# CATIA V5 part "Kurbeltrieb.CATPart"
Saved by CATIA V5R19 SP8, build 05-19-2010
Part number: Kurbeltrieb
Bounding box of the stored display mesh (mm): x -155 to 155, y -203.9 to 203.9, z -24.965 to 24.965
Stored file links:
  C:\Users\schneidp\Desktop\Manikan\V5R19\Kurbeltrieb.CATPart
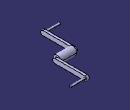
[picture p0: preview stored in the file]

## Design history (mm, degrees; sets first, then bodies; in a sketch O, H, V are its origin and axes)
Body1 (main body)
  Sketch1 on yz-plane, origin (0, 0, 0), H (0, 1, 0), V (0, 0, 1)
    circle A1 centre (0, 0) radius 25
    radius A1 = 25
  Pad1: profile Sketch1, direction (1, 0, 0), length 50, mirrored extent
  Sketch2 on end face of Pad1, origin (50, 0, 0), H (0, 1, 0), V (0, 0, 1)
    construction line L1 (0, 0) -> (190, 0)
    point P1 (190, 0)
    line L2 (0, 13.9001) -> (190, 13.9001)
    line L3 (190, -13.9001) -> (0, -13.9001)
    arc A1 centre (190, 0) radius 13.9001 from (190, 13.9001) to (190, -13.9001) cw
    arc A2 centre (0, 0) radius 13.9001 from (0, -13.9001) to (0, 13.9001) cw
    distance L1 L2 = 13.9001
    distance P1 O = 190
    horizontal: L1 H
    tangency: A1 L2, A2 L2, A1 L3, A2 L3
  Pad2: profile Sketch2, direction (1, 0, 0), length 15
  Sketch3 on start face of Pad1, origin (-50, 0, 0), H (0, -1, 0), V (0, 0, 1)
    construction line L1 (0, 0) -> (190, 0)
    point P1 (190, 0)
    line L2 (0, 13.9) -> (190, 13.9)
    line L3 (190, -13.9) -> (0, -13.9)
    arc A1 centre (190, 0) radius 13.9 from (190, 13.9) to (190, -13.9) cw
    arc A2 centre (0, 0) radius 13.9 from (0, -13.9) to (0, 13.9) cw
    distance L1 L2 = 13.9
    distance P1 O = 190
    horizontal: L1 H
    tangency: A1 L2, A2 L2, A1 L3, A2 L3
  Pad3: profile Sketch3, direction (-1, 0, 0), length 15
  Sketch4 on end face of Pad3, origin (-65, 0, 0), H (0, -1, 0), V (0, 0, 1)
    circle A1 centre (190, 0) radius 6
    point P1 (190, 0)
    radius A1 = 6
    distance V P1 = 190
    coincidence: P1 H
  Pad4: profile Sketch4, direction (-1, 0, 0), length 90
  Sketch5 on end face of Pad2, origin (65, 0, 0), H (0, 1, 0), V (0, 0, 1)
    circle A1 centre (190, 0) radius 6
    point P1 (190, 0)
    point P2 (196, 0)
    radius A1 = 6
    distance P1 V = 190
    coincidence: P1 H, A1 P2, P2 H
  Pad5: profile Sketch5, direction (1, 0, 0), length 90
